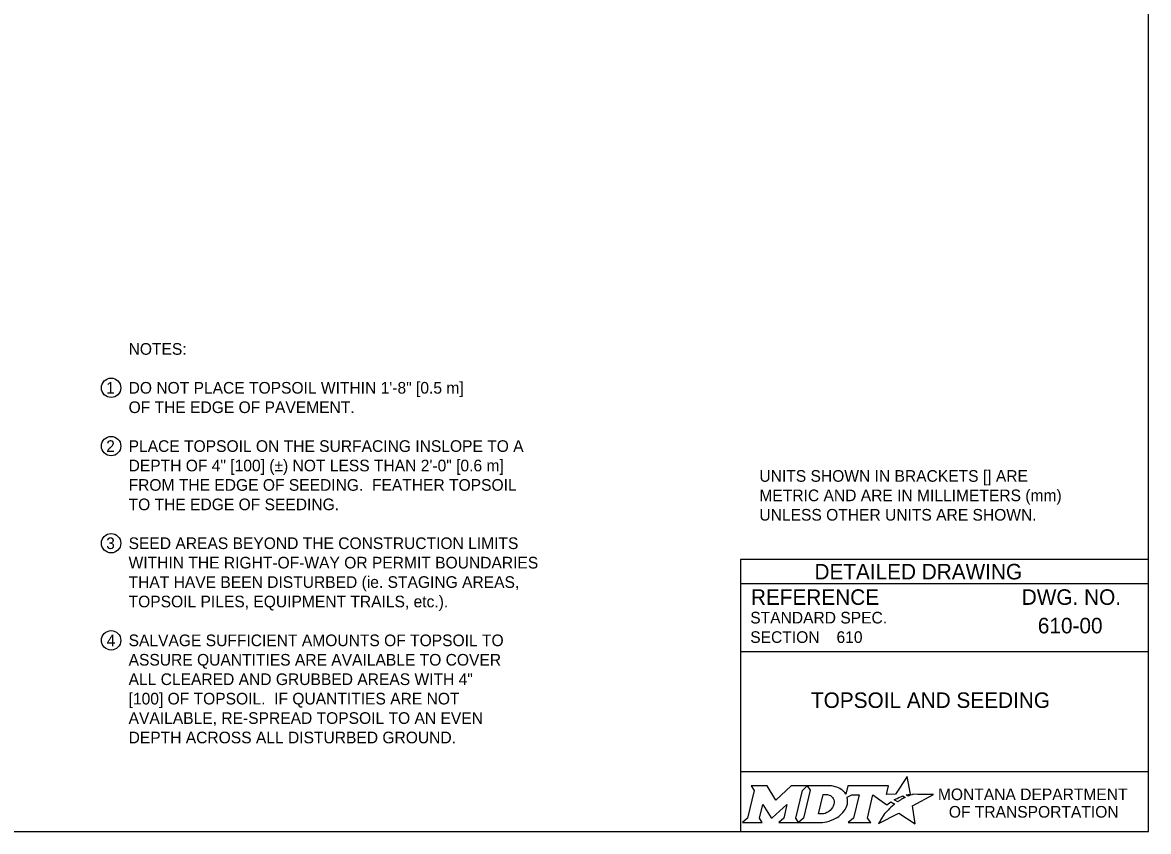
# Model space of a CAD drawing. Extents: x 49991.4 to 50021, y 49987.6 to 50011.4.
# Drawn here: x 50015.14 to 50020.94, y 49999.89 to 50004.05 of the extents above; entities that cross this region are included whole.
import ezdxf

# ---------------------------------------------------------------- set-up
doc = ezdxf.new("R2010")
doc.units = 0
for name, color, linetype in [('Default', 7, 'Continuous'), ('Level 1', 7, 'Continuous'), ('Level 2', 7, 'Continuous'), ('Level 4', 7, 'Continuous')]:
    doc.layers.add(name, color=color, linetype=linetype)

msp = doc.modelspace()

# ---------------------------------------------------------------- linework, layer by layer
at = {"layer": 'Default'}
for points in [[(50019.7003, 50000.0679), (50019.69, 50000.0735), (50019.7016, 50000.0763), (50019.7132, 50000.0783), (50019.6958, 50000.1684), (50019.6363, 50000.0771), (50019.589, 50000.0764), (50019.5993, 50000.1205), (50019.3901, 50000.1206), (50019.38, 50000.0781), (50019.3742, 50000.0864)], [(50018.8933, 50000.1206), (50018.9074, 50000.0972), (50018.8739, 49999.9539), (50018.8482, 49999.9314), (50018.9498, 49999.9314), (50018.9363, 49999.9542), (50018.9525, 50000.0243), (50018.9962, 49999.9553), (50019.0015, 49999.9553), (50019.0766, 50000.0248), (50019.0602, 49999.9537), (50019.0355, 49999.9317), (50019.1371, 49999.9317), (50019.1233, 49999.955), (50019.1565, 50000.0974)], [(50019.1565, 50000.0974), (50019.1818, 50000.1206), (50019.0994, 50000.1206), (50019.0198, 50000.0476), (50018.9753, 50000.1203), (50018.8933, 50000.1206)], [(50019.2954, 50000.1206), (50019.1818, 50000.1206), (50019.1965, 50000.0977), (50019.1626, 49999.9539), (50019.1371, 49999.9317), (50019.2477, 49999.9317)], [(50019.3194, 50000.0339), (50019.3182, 50000.0258), (50019.315, 50000.0165), (50019.3108, 50000.0083), (50019.3052, 50000.0008), (50019.2987, 49999.9939), (50019.2908, 49999.9876), (50019.2825, 49999.9829), (50019.2734, 49999.979), (50019.2643, 49999.9767), (50019.2551, 49999.9758), (50019.2392, 49999.9758), (50019.2628, 50000.0758), (50019.2788, 50000.0758), (50019.2864, 50000.0752), (50019.294, 50000.0733), (50019.3006, 50000.0703), (50019.3067, 50000.0661), (50019.3115, 50000.0611), (50019.3152, 50000.0551), (50019.3179, 50000.0489), (50019.3195, 50000.0415), (50019.3195, 50000.0385), (50019.3194, 50000.0339)], [(50019.3868, 50000.0615), (50019.4114, 50000.0746), (50019.4483, 50000.0746), (50019.4197, 49999.9541), (50019.3922, 49999.9314), (50019.5084, 49999.9314), (50019.4914, 49999.9543), (50019.5196, 50000.0745), (50019.5909, 50000.0228), (50019.612, 50000.0379), (50019.6317, 50000.027)], [(50019.5759, 49999.9711), (50019.5606, 49999.9467), (50019.5559, 49999.9392), (50019.5501, 49999.9306), (50019.5478, 49999.9263), (50019.6531, 49999.9794), (50019.737, 49999.9243), (50019.7239, 50000.017), (50019.8308, 50000.0754), (50019.7815, 50000.0762), (50019.7514, 50000.0766), (50019.7306, 50000.0769), (50019.7238, 50000.0754), (50019.7189, 50000.0742), (50019.7105, 50000.0719), (50019.7003, 50000.0679)], [(50019.6499, 50000.0403), (50019.6475, 50000.0386), (50019.6292, 50000.0482), (50019.6395, 50000.0539), (50019.6436, 50000.0561), (50019.6522, 50000.0601), (50019.6579, 50000.0627), (50019.6658, 50000.0657), (50019.6731, 50000.0684), (50019.6849, 50000.061), (50019.6809, 50000.0589), (50019.6763, 50000.0564), (50019.6721, 50000.0542), (50019.6671, 50000.0513), (50019.6652, 50000.0502), (50019.6625, 50000.0486), (50019.66, 50000.0472), (50019.6577, 50000.0456), (50019.6551, 50000.0438), (50019.6524, 50000.042), (50019.6499, 50000.0403)], [(50019.2934, 49999.939), (50019.3018, 49999.9416), (50019.3148, 49999.947), (50019.3352, 49999.958)], [(50019.5898, 49999.9872), (50019.5898, 49999.9872)]]:
    msp.add_lwpolyline(points, dxfattribs=at)
for centre, radius, start, end in [((50019.2745, 50000.0595), 0.1183, 300.91025, 339.13831), ((50019.3185, 50000.0422), 0.0709, 339.53292, 15.85821)]:
    msp.add_arc(centre, radius, start, end, dxfattribs=at)
for centre, major_axis, ratio, start_param, end_param in [((50019.2933, 50000.0732), (0.0834, -0.0037), 0.568097, 0.61298, 1.570796), ((50019.3489, 50000.0805), (0.0361, -0.0295), 0.469099, 1.225588, 1.570796), ((50019.6206, 50000.0173), (-0.0112, -0.0097), 0.021651, 3.157348, 6.283185), ((50019.5829, 49999.9791), (-0.00694, -0.00806), 0.008222, 0, 3.137361), ((50019.5996, 49999.9974), (-0.0098, -0.0102), 0.016458, 3.141593, 6.279097), ((50019.248, 50000.08), (0, 0.1484), 0.987302, 3.139398, 3.456847)]:
    msp.add_ellipse(centre, major_axis=major_axis, ratio=ratio, start_param=start_param, end_param=end_param, dxfattribs=at)
at = {"layer": 'Level 1'}
msp.add_lwpolyline([(50020.9378, 50008.1646), (50009.7374, 50008.1646), (50009.7374, 49999.8856), (50020.9378, 49999.8856)], close=True, dxfattribs=at)
at = {"layer": 'Level 2'}
for centre in [(50015.5984, 50002.1694), (50015.5984, 50001.8694), (50015.5984, 50001.3694), (50015.5984, 50000.8694)]:
    msp.add_circle(centre, 0.05, dxfattribs=at)
at = {"layer": 'Level 4'}
for p, q in [((50020.9378, 50001.2856), (50018.8378, 50001.2856)), ((50018.8378, 50001.2856), (50018.8378, 49999.8856)), ((50020.9378, 50001.1606), (50018.8378, 50001.1606)), ((50020.5739, 50000.9455), (50020.5739, 50000.9455)), ((50019.3321, 50000.8861), (50019.3321, 50000.8861)), ((50020.9378, 50000.8106), (50018.8378, 50000.8106)), ((50019.8878, 50000.5615), (50019.8878, 50000.5615)), ((50020.9378, 50000.1925), (50018.8378, 50000.1925))]:
    msp.add_line(p, q, dxfattribs=at)

# ---------------------------------------------------------------- texts
at = {"layer": 'Default'}
for s, p in [('MONTANA DEPARTMENT', (50019.854, 50000.0468)), ('OF TRANSPORTATION', (50019.9102, 49999.9568))]:
    msp.add_text(s, height=0.06, dxfattribs=at).set_placement(p)
at = {"layer": 'Level 2'}
for s, height, p in [('NOTES:', 0.06, (50015.6884, 50002.3394)), ('1', 0.06, (50015.5725, 50002.1394)), ('DO NOT PLACE TOPSOIL WITHIN 1\'-8" [0.5 m]', 0.06, (50015.6884, 50002.1394)), ('OF THE EDGE OF PAVEMENT.  ', 0.06, (50015.6884, 50002.0394)), ('2', 0.06, (50015.5732, 50001.8394)), ('PLACE TOPSOIL ON THE SURFACING INSLOPE TO A', 0.06, (50015.6884, 50001.8394)), ('DEPTH OF 4" [100] (±) NOT LESS THAN 2\'-0" [0.6 m]', 0.06, (50015.6884, 50001.7394)), ('FROM THE EDGE OF SEEDING.  FEATHER TOPSOIL', 0.06, (50015.6884, 50001.6394)), ('UNITS SHOWN IN BRACKETS [] ARE ', 0.06, (50018.9353, 50001.6857)), ('METRIC AND ARE IN MILLIMETERS (mm) ', 0.06, (50018.9353, 50001.5857)), ('TO THE EDGE OF SEEDING.', 0.06, (50015.6884, 50001.5394)), ('UNLESS OTHER UNITS ARE SHOWN.', 0.06, (50018.9353, 50001.4857)), ('3', 0.06, (50015.5732, 50001.3394)), ('SEED AREAS BEYOND THE CONSTRUCTION LIMITS ', 0.06, (50015.6884, 50001.3394)), ('WITHIN THE RIGHT-OF-WAY OR PERMIT BOUNDARIES', 0.06, (50015.6884, 50001.2394)), ('THAT HAVE BEEN DISTURBED (ie. STAGING AREAS, ', 0.06, (50015.6884, 50001.1394)), ('TOPSOIL PILES, EQUIPMENT TRAILS, etc.).', 0.06, (50015.6884, 50001.0394)), ('610-00', 0.08, (50020.3683, 50000.9055)), ('4', 0.06, (50015.5757, 50000.8394)), ('SALVAGE SUFFICIENT AMOUNTS OF TOPSOIL TO', 0.06, (50015.6884, 50000.8394)), ('610', 0.06, (50019.3321, 50000.8561)), ('ASSURE QUANTITIES ARE AVAILABLE TO COVER ', 0.06, (50015.6884, 50000.7394)), ('ALL CLEARED AND GRUBBED AREAS WITH 4" ', 0.06, (50015.6884, 50000.6394)), ('[100] OF TOPSOIL.  IF QUANTITIES ARE NOT ', 0.06, (50015.6884, 50000.5394)), ('TOPSOIL AND SEEDING', 0.08, (50019.2005, 50000.5215)), ('AVAILABLE, RE-SPREAD TOPSOIL TO AN EVEN ', 0.06, (50015.6884, 50000.4394)), ('DEPTH ACROSS ALL DISTURBED GROUND.', 0.06, (50015.6884, 50000.3394))]:
    msp.add_text(s, height=height, dxfattribs=at).set_placement(p)
at = {"layer": 'Level 4'}
for s, height, p in [('DETAILED DRAWING', 0.0799, (50019.2188, 50001.1831)), ('REFERENCE', 0.08, (50018.8914, 50001.0522)), ('DWG. NO.', 0.08, (50020.2856, 50001.0522)), ('STANDARD SPEC.', 0.06, (50018.8881, 50000.9562)), ('SECTION', 0.06, (50018.8881, 50000.8562))]:
    msp.add_text(s, height=height, dxfattribs=at).set_placement(p)

doc.saveas('drawing.dxf')
